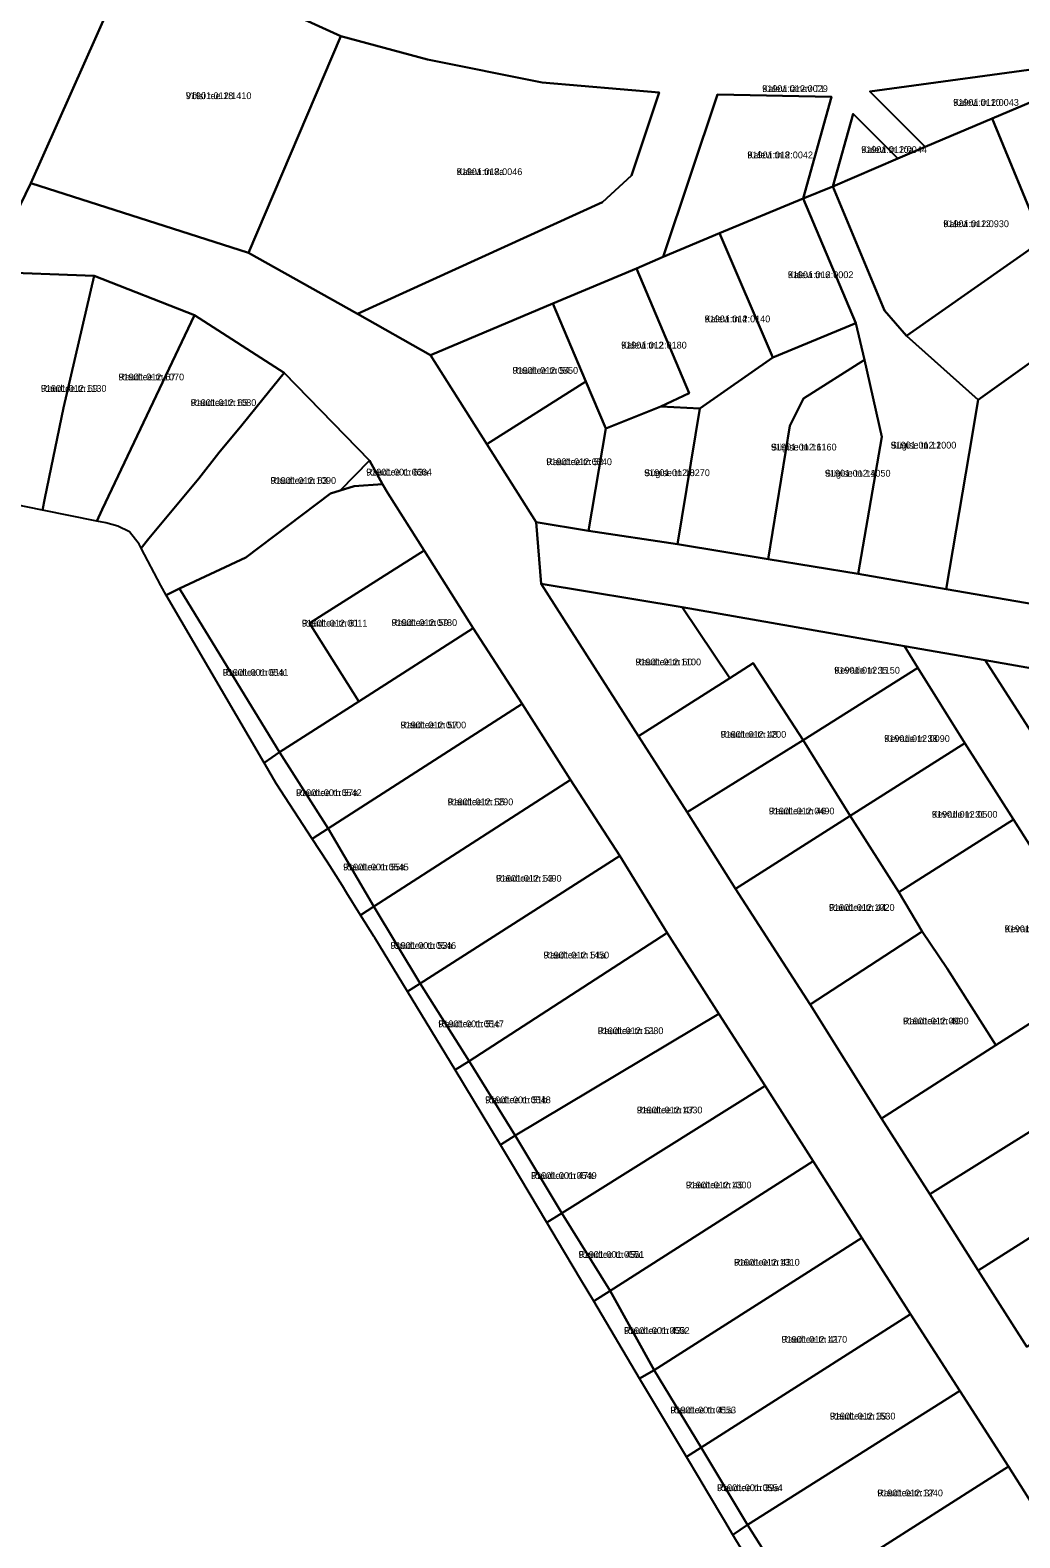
# Model space of a CAD drawing. Extents: x 675810 to 681273, y 6411190 to 6417565.
# Drawn here: x 678218.5 to 678437.2, y 6413720.5 to 6414053.8 of the extents above; entities that cross this region are included whole.
import ezdxf

# ---------------------------------------------------------------- set-up
doc = ezdxf.new("R2010")
doc.units = 0
for name, color, linetype in [('L_AADRESS', 7, 'Continuous'), ('PIIR', 7, 'Continuous'), ('TUNNUS', 7, 'Continuous')]:
    doc.layers.add(name, color=color, linetype=linetype)

msp = doc.modelspace()

# ---------------------------------------------------------------- linework, layer by layer
at = {"layer": 'PIIR'}
for points in [[(678242.2, 6414072.95), (678218.66, 6414020), (678209.09, 6414000.34)], [(678439.84, 6414062.16), (678447.32, 6414046.14), (678404.04, 6414040.23), (678416.31, 6414027.98), (678410.26, 6414025.4), (678400.35, 6414035.3), (678395.84, 6414019.23), (678389.31, 6414016.6), (678395.59, 6414039.05), (678370.36, 6414039.6), (678358.38, 6414003.67), (678352.46, 6414001.13), (678334.04, 6413993.38), (678306.95, 6413981.95), (678290.84, 6413991.05), (678344.97, 6414015.74), (678351.41, 6414021.65), (678357.53, 6414040.01), (678331.66, 6414042.24), (678306.31, 6414047.32), (678287.14, 6414052.45), (678242.2, 6414072.95)], [(678459.09, 6413697.62), (678434.67, 6413736.25), (678423.93, 6413752.97), (678413.03, 6413769.95), (678402.31, 6413786.79), (678391.54, 6413803.78), (678380.96, 6413820.4), (678370.66, 6413836.34), (678359.3, 6413854.27), (678348.79, 6413871.23), (678337.9, 6413888.08), (678327.26, 6413904.83), (678316.39, 6413921.57), (678305.57, 6413938.77), (678297.57, 6413951.43), (678296.34, 6413953.43), (678293.5, 6413958.65), (678274.67, 6413978.05), (678254.85, 6413990.77), (678232.67, 6413999.48), (678209.09, 6414000.34), (678218.66, 6414020), (678266.75, 6414004.56), (678290.84, 6413991.05), (678306.95, 6413981.95), (678319.42, 6413962.26), (678330.34, 6413945.03), (678331.41, 6413931.37), (678352.94, 6413897.74), (678363.66, 6413880.89), (678374.39, 6413863.99), (678390.86, 6413838.39), (678406.61, 6413813.23), (678417.3, 6413796.48), (678428.02, 6413779.57), (678438.75, 6413762.72)]]:
    msp.add_lwpolyline(points, dxfattribs=at)
for points in [[(678242.2, 6414072.95), (678287.14, 6414052.45), (678266.75, 6414004.56), (678218.66, 6414020)], [(678287.14, 6414052.45), (678306.31, 6414047.32), (678331.66, 6414042.24), (678357.53, 6414040.01), (678351.41, 6414021.65), (678344.97, 6414015.74), (678290.84, 6413991.05), (678266.75, 6414004.56)], [(678404.04, 6414040.23), (678447.32, 6414046.14), (678449.23, 6414041.96), (678431.1, 6414034.24), (678416.31, 6414027.98)], [(678370.36, 6414039.6), (678395.59, 6414039.05), (678389.31, 6414016.6), (678370.86, 6414008.91), (678358.38, 6414003.67)], [(678462.89, 6414021.78), (678442.2, 6414007.27), (678431.1, 6414034.24), (678449.23, 6414041.96)], [(678395.84, 6414019.23), (678400.35, 6414035.3), (678410.26, 6414025.4)], [(678431.1, 6414034.24), (678442.2, 6414007.27), (678412.15, 6413986.24), (678407.31, 6413991.8), (678395.84, 6414019.23), (678410.26, 6414025.4), (678416.31, 6414027.98)], [(678389.31, 6414016.6), (678395.84, 6414019.23), (678407.31, 6413991.8), (678412.15, 6413986.24), (678428.01, 6413972.09), (678426, 6413960.19), (678420.93, 6413930.19), (678401.49, 6413933.61), (678406.67, 6413963.86), (678402.87, 6413980.9), (678400.98, 6413989)], [(678473.89, 6414006.35), (678450.83, 6413988.67), (678442.46, 6413982.42), (678428.01, 6413972.09), (678412.15, 6413986.24), (678442.2, 6414007.27), (678462.89, 6414021.78)], [(678370.86, 6414008.91), (678389.31, 6414016.6), (678400.98, 6413989), (678382.63, 6413981.39)], [(678370.86, 6414008.91), (678382.63, 6413981.39), (678366.51, 6413970.18), (678357.85, 6413970.62), (678364.14, 6413973.51), (678352.46, 6414001.13), (678358.38, 6414003.67)], [(678225.9, 6413970.33), (678221.72, 6413950.36), (678221.21, 6413947.69), (678209.31, 6413950.08), (678209.35, 6413952.33), (678209.53, 6413970.34), (678209.48, 6413975.6), (678209.17, 6413982.58), (678209.09, 6414000.34), (678232.67, 6413999.48)], [(678254.85, 6413990.77), (678234.46, 6413947.85), (678233.28, 6413945.27), (678221.21, 6413947.69), (678221.72, 6413950.36), (678225.9, 6413970.33), (678232.67, 6413999.48)], [(678341.3, 6413976.15), (678334.04, 6413993.38), (678352.46, 6414001.13), (678364.14, 6413973.51), (678357.85, 6413970.62), (678345.7, 6413965.73)], [(678334.04, 6413993.38), (678341.3, 6413976.15), (678319.42, 6413962.26), (678306.95, 6413981.95)], [(678244.76, 6413941.41), (678243.05, 6413939.3), (678242.6, 6413940.14), (678240.48, 6413942.86), (678237.88, 6413944.14), (678235.27, 6413944.86), (678233.28, 6413945.27), (678234.46, 6413947.85), (678254.85, 6413990.77), (678274.67, 6413978.05), (678269.93, 6413972.2), (678265.3, 6413966.48), (678260.22, 6413960.37), (678255.79, 6413954.65)], [(678382.63, 6413981.39), (678400.98, 6413989), (678402.87, 6413980.9), (678389.39, 6413972.39), (678386.41, 6413966.34), (678381.59, 6413936.81), (678361.56, 6413940.14), (678366.51, 6413970.18)], [(678428.01, 6413972.09), (678442.46, 6413982.41), (678453.73, 6413966.46), (678462.72, 6413953.96), (678445.45, 6413956.43), (678440.59, 6413926.81), (678420.93, 6413930.19), (678426, 6413960.19)], [(678389.39, 6413972.39), (678402.87, 6413980.9), (678406.67, 6413963.86), (678401.49, 6413933.61), (678381.59, 6413936.81), (678386.41, 6413966.34)], [(678269.93, 6413972.2), (678274.67, 6413978.05), (678293.5, 6413958.65), (678286.98, 6413952.02), (678284.9, 6413951.36), (678266.14, 6413937.21), (678251.51, 6413930.38), (678248.53, 6413928.9), (678247.39, 6413931.06), (678243.05, 6413939.3), (678244.76, 6413941.41), (678255.79, 6413954.65), (678260.22, 6413960.37), (678265.3, 6413966.48)], [(678341.3, 6413976.15), (678345.7, 6413965.73), (678341.89, 6413943.13), (678330.34, 6413945.03), (678319.42, 6413962.26)], [(678341.89, 6413943.13), (678345.7, 6413965.73), (678357.85, 6413970.62), (678366.51, 6413970.18), (678361.56, 6413940.14)], [(678296.34, 6413953.43), (678290.08, 6413953), (678286.98, 6413952.02), (678293.5, 6413958.65)], [(678297.57, 6413951.43), (678305.57, 6413938.77), (678280.24, 6413922.68), (678291.12, 6413905.38), (678273.62, 6413894.17), (678251.81, 6413929.84), (678251.51, 6413930.38), (678266.14, 6413937.21), (678284.9, 6413951.36), (678286.98, 6413952.02), (678290.08, 6413953), (678296.34, 6413953.43)], [(678330.34, 6413945.03), (678341.89, 6413943.13), (678361.56, 6413940.14), (678381.59, 6413936.81), (678401.49, 6413933.61), (678420.93, 6413930.19), (678440.59, 6413926.81), (678460.33, 6413923.61), (678480.38, 6413919.98), (678499.93, 6413915.74), (678528.98, 6413909.5), (678542.68, 6413912.5), (678555.72, 6413894.78), (678549.27, 6413893.41), (678429.5, 6413914.49), (678411.69, 6413917.59), (678362.56, 6413926.23), (678331.41, 6413931.37)], [(678305.57, 6413938.77), (678316.39, 6413921.57), (678291.12, 6413905.38), (678280.24, 6413922.68)], [(678248.53, 6413928.9), (678251.51, 6413930.38), (678251.81, 6413929.84), (678273.62, 6413894.17), (678270.19, 6413891.82)], [(678352.94, 6413897.74), (678331.41, 6413931.37), (678362.56, 6413926.23), (678373.11, 6413910.52)], [(678411.69, 6413917.59), (678414.63, 6413912.8), (678389.31, 6413896.85), (678378.27, 6413913.83), (678373.11, 6413910.52), (678362.56, 6413926.23)], [(678327.26, 6413904.83), (678284.36, 6413877.31), (678273.62, 6413894.17), (678291.12, 6413905.38), (678316.39, 6413921.57)], [(678411.69, 6413917.59), (678429.5, 6413914.49), (678469.14, 6413852.8), (678485.25, 6413827.78), (678501.14, 6413802.16), (678511.94, 6413785.53), (678522.67, 6413768.65), (678526.43, 6413762.74), (678541.98, 6413738.26), (678529.34, 6413732.11), (678526.12, 6413737.17), (678500.14, 6413777.83), (678489.4, 6413794.9), (678478.68, 6413811.78), (678468.27, 6413828.33), (678457.22, 6413845.53), (678435.77, 6413879.29), (678425.05, 6413896.17), (678414.63, 6413912.8)], [(678363.66, 6413880.89), (678352.94, 6413897.74), (678373.11, 6413910.52), (678378.27, 6413913.83), (678389.31, 6413896.85)], [(678389.31, 6413896.85), (678414.63, 6413912.8), (678425.05, 6413896.17), (678399.72, 6413880.08)], [(678429.5, 6413914.49), (678549.27, 6413893.41), (678523.76, 6413887.76), (678523, 6413888.82), (678507.85, 6413879.34), (678491.9, 6413869.36), (678469.14, 6413852.8)], [(678337.9, 6413888.08), (678294.45, 6413860.05), (678284.36, 6413877.31), (678327.26, 6413904.83)], [(678374.39, 6413863.99), (678363.66, 6413880.89), (678389.31, 6413896.85), (678399.72, 6413880.08)], [(678435.77, 6413879.29), (678410.45, 6413863.2), (678399.72, 6413880.08), (678425.05, 6413896.17)], [(678270.19, 6413891.82), (678273.62, 6413894.17), (678284.36, 6413877.31), (678280.86, 6413875.03), (678272.86, 6413887.24), (678270.42, 6413891.44)], [(678348.79, 6413871.23), (678304.72, 6413843.01), (678294.45, 6413860.05), (678337.9, 6413888.08)], [(678374.39, 6413863.99), (678399.72, 6413880.08), (678410.45, 6413863.2), (678415.64, 6413854.51), (678390.86, 6413838.39)], [(678431.9, 6413829.44), (678421.17, 6413846.32), (678415.64, 6413854.51), (678410.45, 6413863.2), (678435.77, 6413879.29), (678457.22, 6413845.53)], [(678291.54, 6413858.18), (678288.51, 6413863.03), (678287.5, 6413864.65), (678284.23, 6413869.87), (678280.86, 6413875.03), (678284.36, 6413877.31), (678294.45, 6413860.05)], [(678359.3, 6413854.27), (678315.53, 6413825.9), (678304.72, 6413843.01), (678348.79, 6413871.23)], [(678291.54, 6413858.18), (678294.45, 6413860.05), (678304.72, 6413843.01), (678301.86, 6413841.3), (678294.68, 6413853.14), (678294.53, 6413853.38)], [(678370.66, 6413836.34), (678325.71, 6413809.43), (678315.53, 6413825.9), (678359.3, 6413854.27)], [(678390.86, 6413838.39), (678415.64, 6413854.51), (678421.17, 6413846.32), (678431.9, 6413829.44), (678406.61, 6413813.23)], [(678301.86, 6413841.3), (678304.72, 6413843.01), (678315.53, 6413825.9), (678312.4, 6413823.92)], [(678431.9, 6413829.44), (678457.22, 6413845.53), (678468.27, 6413828.33), (678417.3, 6413796.48), (678406.61, 6413813.23)], [(678380.96, 6413820.4), (678335.99, 6413792.29), (678325.71, 6413809.43), (678370.66, 6413836.34)], [(678312.4, 6413823.92), (678315.53, 6413825.9), (678325.71, 6413809.43), (678322.41, 6413807.4)], [(678417.3, 6413796.48), (678468.27, 6413828.33), (678478.68, 6413811.78), (678453.35, 6413795.69), (678428.02, 6413779.57)], [(678380.96, 6413820.4), (678391.54, 6413803.78), (678346.7, 6413775.09), (678335.99, 6413792.29)], [(678324.88, 6413803.33), (678322.41, 6413807.4), (678325.71, 6413809.43), (678335.99, 6413792.29), (678332.7, 6413790.18)], [(678346.7, 6413775.09), (678391.54, 6413803.78), (678402.31, 6413786.79), (678356.43, 6413757.54)], [(678464.07, 6413778.81), (678438.75, 6413762.72), (678428.02, 6413779.57), (678453.35, 6413795.69)], [(678332.7, 6413790.18), (678335.99, 6413792.29), (678346.7, 6413775.09), (678343.05, 6413772.79), (678340.15, 6413777.67), (678335.06, 6413786.22)], [(678413.03, 6413769.95), (678366.77, 6413740.45), (678356.43, 6413757.54), (678402.31, 6413786.79)], [(678343.05, 6413772.79), (678346.7, 6413775.09), (678356.43, 6413757.54), (678353.19, 6413755.74)], [(678423.93, 6413752.97), (678377.05, 6413723.35), (678366.77, 6413740.45), (678413.03, 6413769.95)], [(678353.19, 6413755.74), (678356.43, 6413757.54), (678366.77, 6413740.45), (678363.52, 6413738.38)], [(678434.67, 6413736.25), (678387.78, 6413706.37), (678377.05, 6413723.35), (678423.93, 6413752.97)], [(678368.16, 6413730.6), (678366.23, 6413733.84), (678363.52, 6413738.38), (678366.77, 6413740.45), (678377.05, 6413723.35), (678373.78, 6413721.16), (678371.98, 6413724.18)], [(678434.67, 6413736.25), (678459.09, 6413697.62), (678408.15, 6413673.4), (678387.78, 6413706.37)], [(678384.37, 6413704.1), (678378.59, 6413713.37), (678374.42, 6413720.08), (678373.78, 6413721.16), (678377.05, 6413723.35), (678387.78, 6413706.37)]]:
    msp.add_lwpolyline(points, close=True, dxfattribs=at)

# ---------------------------------------------------------------- texts
at = {"layer": 'L_AADRESS'}
for s, p in [('Võlsi tee 18', (678252.9, 6414038.54)), ('Kalevi tänav T1', (678380.27, 6414040.11)), ('Kalevi tn 10', (678422.47, 6414037.06)), ('Kalevi tn 8', (678376.99, 6414025.46)), ('Kalevi tn 10a', (678402.15, 6414026.64)), ('Kalevi tn 8a', (678312.76, 6414021.75)), ('Kalevi tn 12', (678420.29, 6414010.24)), ('Kalevi tn 6', (678385.92, 6413998.97)), ('Kalevi tn 4', (678367.55, 6413989.21)), ('Kalevi tn 2', (678349.09, 6413983.4)), ('Raudtee tn 54', (678325.08, 6413977.82)), ('Raudtee tn 67', (678238.03, 6413976.37)), ('Raudtee tn 69', (678220.88, 6413973.83)), ('Raudtee tn 65', (678253.98, 6413970.7)), ('Sügise tn 16', (678382.21, 6413960.87)), ('Sügise tn 12', (678408.66, 6413961.3)), ('Raudtee tn 52', (678332.56, 6413957.63)), ('Raudtee tn 63a', (678292.77, 6413955.33)), ('Sügise tn 18', (678354.2, 6413955.2)), ('Sügise tn 14', (678394.13, 6413955.09)), ('Raudtee tn 63', (678271.61, 6413953.48)), ('Raudtee tn 61', (678278.54, 6413921.94)), ('Raudtee tn 59', (678298.35, 6413922.07)), ('Raudtee tn 61a', (678261.07, 6413911.06)), ('Raudtee tn 50', (678352.26, 6413913.37)), ('Kevade tn 35', (678396.19, 6413911.54)), ('Raudtee tn 57', (678300.35, 6413899.44)), ('Raudtee tn 48', (678371.08, 6413897.36)), ('Kevade tn 33', (678407.22, 6413896.44)), ('Raudtee tn 57a', (678277.27, 6413884.47)), ('Raudtee tn 55', (678310.76, 6413882.44)), ('Raudtee tn 46', (678381.73, 6413880.42)), ('Kevade tn 31', (678417.75, 6413879.69)), ('Raudtee tn 55a', (678287.66, 6413868.04)), ('Raudtee tn 53', (678321.44, 6413865.54)), ('Raudtee tn 44', (678395.02, 6413859.09)), ('Kevade tn 29', (678433.84, 6413854.37)), ('Raudtee tn 53a', (678298.13, 6413850.7)), ('Raudtee tn 51a', (678331.95, 6413848.57)), ('Raudtee tn 51c', (678308.7, 6413833.37)), ('Raudtee tn 51', (678343.93, 6413831.85)), ('Raudtee tn 40', (678411.38, 6413834.01)), ('Raudtee tn 51b', (678319.05, 6413816.57)), ('Raudtee tn 47', (678352.55, 6413814.32)), ('Raudtee tn 47a', (678329.2, 6413799.84)), ('Raudtee tn 45', (678363.41, 6413797.74)), ('Raudtee tn 45a', (678339.7, 6413782.38)), ('Raudtee tn 43', (678374.05, 6413780.66)), ('Raudtee tn 43a', (678349.74, 6413765.57)), ('Raudtee tn 41', (678384.54, 6413763.62)), ('Raudtee tn 41a', (678359.98, 6413748)), ('Raudtee tn 39', (678395.21, 6413746.65)), ('Raudtee tn 39a', (678370.29, 6413730.82)), ('Raudtee tn 37', (678405.7, 6413729.67))]:
    msp.add_text(s, height=1.5, dxfattribs=at).set_placement(p)
at = {"layer": 'TUNNUS'}
for s, p in [('91901:012:1410', (678252.9, 6414038.54)), ('91901:012:0029', (678380.27, 6414040.11)), ('91901:012:0043', (678422.47, 6414037.06)), ('91901:012:0042', (678376.99, 6414025.46)), ('91901:012:0044', (678402.15, 6414026.64)), ('91901:012:0046', (678312.76, 6414021.75)), ('91901:012:0930', (678420.29, 6414010.24)), ('91901:012:0002', (678385.92, 6413998.97)), ('91901:012:0140', (678367.55, 6413989.21)), ('91901:012:0180', (678349.09, 6413983.4)), ('91901:012:0550', (678325.08, 6413977.82)), ('91901:012:1070', (678238.03, 6413976.37)), ('91901:012:1130', (678220.88, 6413973.83)), ('91901:012:1080', (678253.98, 6413970.7)), ('91901:012:1160', (678382.21, 6413960.87)), ('91901:012:1000', (678408.66, 6413961.3)), ('91901:012:0540', (678332.56, 6413957.63)), ('91901:001:0664', (678292.77, 6413955.33)), ('91901:012:0270', (678354.2, 6413955.2)), ('91901:012:1050', (678394.13, 6413955.09)), ('91901:012:1090', (678271.61, 6413953.48)), ('91901:012:0011', (678278.54, 6413921.94)), ('91901:012:0780', (678298.35, 6413922.07)), ('91901:001:0541', (678261.07, 6413911.06)), ('91901:012:1100', (678352.26, 6413913.37)), ('91901:012:1150', (678396.19, 6413911.54)), ('91901:012:0100', (678300.35, 6413899.44)), ('91901:012:1200', (678371.08, 6413897.36)), ('91901:012:0090', (678407.22, 6413896.44)), ('91901:001:0542', (678277.27, 6413884.47)), ('91901:012:1290', (678310.76, 6413882.44)), ('91901:012:0490', (678381.73, 6413880.42)), ('91901:012:0500', (678417.75, 6413879.69)), ('91901:001:0545', (678287.66, 6413868.04)), ('91901:012:1490', (678321.44, 6413865.54)), ('91901:012:1020', (678395.02, 6413859.09)), ('91901:012:0200', (678433.84, 6413854.37)), ('91901:001:0546', (678298.13, 6413850.7)), ('91901:012:1450', (678331.95, 6413848.57)), ('91901:001:0547', (678308.7, 6413833.37)), ('91901:012:1280', (678343.93, 6413831.85)), ('91901:012:0990', (678411.38, 6413834.01)), ('91901:001:0548', (678319.05, 6413816.57)), ('91901:012:1330', (678352.55, 6413814.32)), ('91901:001:0549', (678329.2, 6413799.84)), ('91901:012:1300', (678363.41, 6413797.74)), ('91901:001:0551', (678339.7, 6413782.38)), ('91901:012:1310', (678374.05, 6413780.66)), ('91901:001:0552', (678349.74, 6413765.57)), ('91901:012:1270', (678384.54, 6413763.62)), ('91901:001:0553', (678359.98, 6413748)), ('91901:012:1530', (678395.21, 6413746.65)), ('91901:001:0554', (678370.29, 6413730.82)), ('91901:012:1240', (678405.7, 6413729.67))]:
    msp.add_text(s, height=1.5, dxfattribs=at).set_placement(p)

doc.saveas('drawing.dxf')
